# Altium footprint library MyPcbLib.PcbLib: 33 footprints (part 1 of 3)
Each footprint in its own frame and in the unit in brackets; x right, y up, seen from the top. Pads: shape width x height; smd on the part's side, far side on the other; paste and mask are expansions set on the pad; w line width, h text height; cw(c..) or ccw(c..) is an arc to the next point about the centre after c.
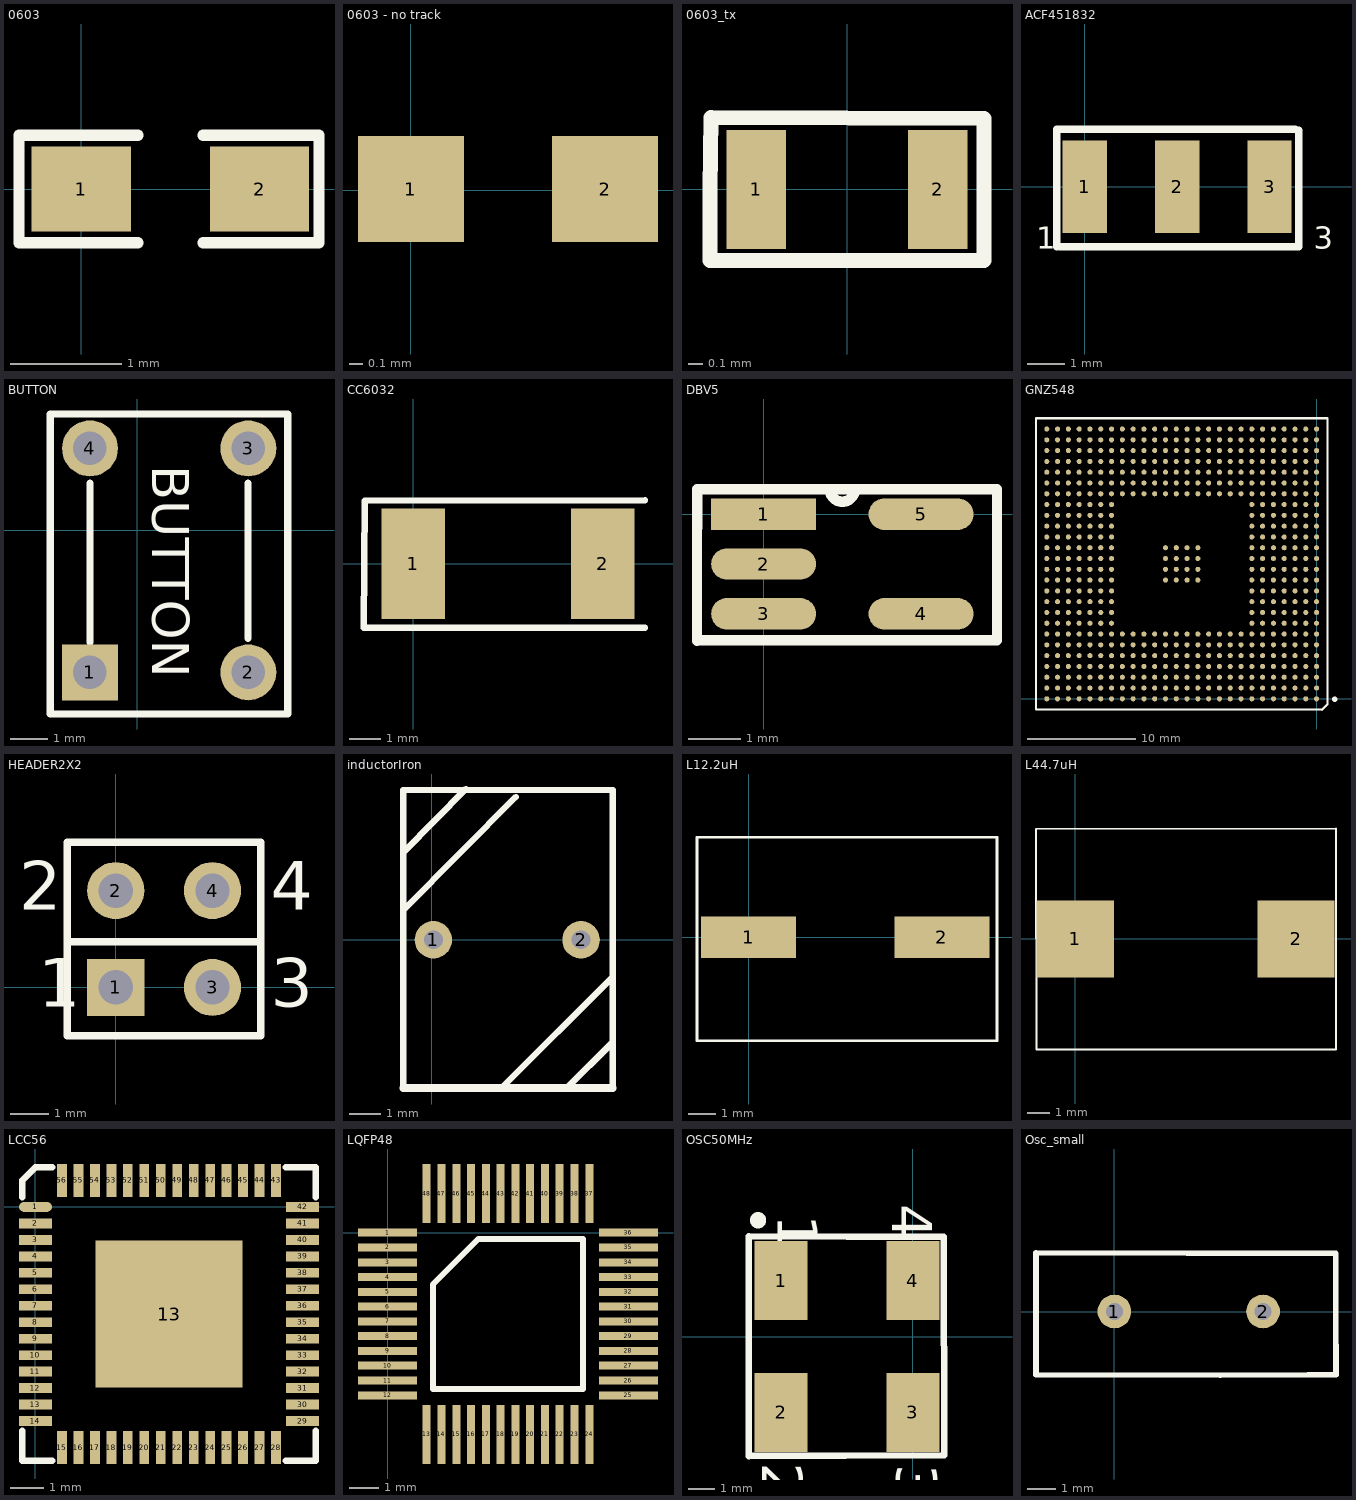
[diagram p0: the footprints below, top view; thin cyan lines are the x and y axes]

## 0603 [mil] "for DSP"
pads (2):
  rect 35x30 smd: 1(0,0) 2(62.99,0)
Top Overlay:
  lines w3.94: 20,-19 -22,-19 -22,19 20,19 ; 43,-19 84,-19 84,19 43,19

## 0603 - no track [mil]
pads (2):
  rect 30x30 smd: 1(0,0.33) 2(55,0.33)

## 0603_tx [mm]
pads (2):
  rect 0.4x0.8 smd: 1(-0.61,0) 2(0.61,0)
Top Overlay:
  lines w0.1: -0.922,-0.478 0.922,-0.478 0.922,0.478 -0.914,0.483 -0.922,0 -0.922,-0.478

## ACF451832 [mm] "for ACF451832-333-T"
pads (3):
  rect 1.2x2.5 smd: 1(0,0) 2(2.5,0) 3(5,0)
Top Overlay:
  lines w0.2: -0.762,-1.626 -0.762,1.524 ; -0.762,1.549 5.69,1.549 ; -0.686,-1.626 5.791,-1.626 5.791,1.524
  text "3" at 6.198,-1.676 h0.6
  text "1" at -1.321,-1.676 h0.6

## BUTTON [mm]
pads (4):
  rect 1.5x1.5 hole 0.9: 1(-1.27,-3.81)
  round 1.5 hole 0.9: 2(2.98,-3.81) 3(2.98,2.2) 4(-1.27,2.2)
Top Overlay:
  lines w0.2: -1.27,-2.997 -1.27,1.27 ; 2.972,-2.896 2.972,1.27 ; -2.337,-4.928 -2.337,3.124 4.039,3.124 4.039,-4.928 -2.337,-4.928
  text "BUTTON" at 0.406,1.753 h1

## CC6032 [mm] "for 100uF"
pads (2):
  rect 2x3.5 smd: 1(0,0) 2(6,0)
Top Overlay:
  lines w0.2: 7.341,-2.032 -1.564,-2.035 -1.539,1.984 7.341,2.007

## DBV5 [mm] "DBV5;DBV (R-PDSO-G5);PSO;for TPS3823-33"
pads (5):
  rect 2x0.6 smd: 1(0,0)
  oval 2x0.6 smd: 2(0,-0.95) 3(0,-1.9) 4(3,-1.9) 5(3,0)
Top Overlay:
  lines w0.2: -1.27,-2.413 -1.27,-1.067 -1.269,0.475 1.737,0.475 cw(c1.5,0.475) 1.262,0.475 4.447,0.475 4.447,-2.4 -1.257,-2.4

## GNZ548 [mm] "BGA;548 Balls;Body 27 x 27 mm;for DM642"
height 2.8
pads (548):
  round 0.47 smd: A1(0,0) A2(-1,0) A3(-2,0) A4(-3,0) A5(-4,0) A6(-5,0) A7(-6,0) A8(-7,0) A9(-8,0) A10(-9,0) A11(-10,0) A12(-11,0) A13(-12,0) A14(-13,0) A15(-14,0) A16(-15,0) A17(-16,0) A18(-17,0) A19(-18,0) A20(-19,0) A21(-20,0) A22(-21,0) A23(-22,0) A24(-23,0) A25(-24,0) A26(-25,0) AA1(0,20) AA2(-1,20) AA3(-2,20) AA4(-3,20) AA5(-4,20) AA6(-5,20) AA7(-6,20) AA8(-7,20) AA9(-8,20) AA10(-9,20) AA11(-10,20) AA12(-11,20) AA13(-12,20) AA14(-13,20) AA15(-14,20) AA16(-15,20) AA17(-16,20) AA18(-17,20) AA19(-18,20) AA20(-19,20) AA21(-20,20) AA22(-21,20) AA23(-22,20) AA24(-23,20) AA25(-24,20) AA26(-25,20) AB1(0,21) AB2(-1,21) AB3(-2,21) AB4(-3,21) AB5(-4,21) AB6(-5,21) AB7(-6,21) AB8(-7,21) AB9(-8,21) AB10(-9,21) AB11(-10,21) AB12(-11,21) AB13(-12,21) AB14(-13,21) AB15(-14,21) AB16(-15,21) AB17(-16,21) AB18(-17,21) AB19(-18,21) AB20(-19,21) AB21(-20,21) AB22(-21,21) AB23(-22,21) AB24(-23,21) AB25(-24,21) AB26(-25,21) AC1(0,22) AC2(-1,22) AC3(-2,22) AC4(-3,22) AC5(-4,22) AC6(-5,22) AC7(-6,22) AC8(-7,22) AC9(-8,22) AC10(-9,22) AC11(-10,22) AC12(-11,22) AC13(-12,22) AC14(-13,22) AC15(-14,22) AC16(-15,22) AC17(-16,22) AC18(-17,22) AC19(-18,22) AC20(-19,22) AC21(-20,22) AC22(-21,22) AC23(-22,22) AC24(-23,22) AC25(-24,22) AC26(-25,22) AD1(0,23) AD2(-1,23) AD3(-2,23) AD4(-3,23) AD5(-4,23) AD6(-5,23) AD7(-6,23) AD8(-7,23) AD9(-8,23) AD10(-9,23) AD11(-10,23) AD12(-11,23) AD13(-12,23) AD14(-13,23) AD15(-14,23) AD16(-15,23) AD17(-16,23) AD18(-17,23) AD19(-18,23) AD20(-19,23) AD21(-20,23) AD22(-21,23) AD23(-22,23) AD24(-23,23) AD25(-24,23) AD26(-25,23) AE1(0,24) AE2(-1,24) AE3(-2,24) AE4(-3,24) AE5(-4,24) AE6(-5,24) AE7(-6,24) AE8(-7,24) AE9(-8,24) AE10(-9,24) AE11(-10,24) AE12(-11,24) AE13(-12,24) AE14(-13,24) AE15(-14,24) AE16(-15,24) AE17(-16,24) AE18(-17,24) AE19(-18,24) AE20(-19,24) AE21(-20,24) AE22(-21,24) AE23(-22,24) AE24(-23,24) AE25(-24,24) AE26(-25,24) AF1(0,25) AF2(-1,25) AF3(-2,25) AF4(-3,25) AF5(-4,25) AF6(-5,25) AF7(-6,25) AF8(-7,25) AF9(-8,25) AF10(-9,25) AF11(-10,25) AF12(-11,25) AF13(-12,25) AF14(-13,25) AF15(-14,25) AF16(-15,25) AF17(-16,25) AF18(-17,25) AF19(-18,25) AF20(-19,25) AF21(-20,25) AF22(-21,25) AF23(-22,25) AF24(-23,25) AF25(-24,25) AF26(-25,25) B1(0,1) B2(-1,1) B3(-2,1) B4(-3,1) B5(-4,1) B6(-5,1) B7(-6,1) B8(-7,1) B9(-8,1) B10(-9,1) B11(-10,1) B12(-11,1) B13(-12,1) B14(-13,1) B15(-14,1) B16(-15,1) B17(-16,1) B18(-17,1) B19(-18,1) B20(-19,1) B21(-20,1) B22(-21,1) B23(-22,1) B24(-23,1) B25(-24,1) B26(-25,1) C1(0,2) C2(-1,2) C3(-2,2) C4(-3,2) C5(-4,2) C6(-5,2) C7(-6,2) C8(-7,2) C9(-8,2) C10(-9,2) C11(-10,2) C12(-11,2) C13(-12,2) C14(-13,2) C15(-14,2) C16(-15,2) C17(-16,2) C18(-17,2) C19(-18,2) C20(-19,2) C21(-20,2) C22(-21,2) C23(-22,2) C24(-23,2) C25(-24,2) C26(-25,2) D1(0,3) D2(-1,3) D3(-2,3) D4(-3,3) D5(-4,3) D6(-5,3) D7(-6,3) D8(-7,3) D9(-8,3) D10(-9,3) D11(-10,3) D12(-11,3) D13(-12,3) D14(-13,3) D15(-14,3) D16(-15,3) D17(-16,3) D18(-17,3) D19(-18,3) D20(-19,3) D21(-20,3) D22(-21,3) D23(-22,3) D24(-23,3) D25(-24,3) D26(-25,3) E1(0,4) E2(-1,4) E3(-2,4) E4(-3,4) E5(-4,4) E6(-5,4) E7(-6,4) E8(-7,4) E9(-8,4) E10(-9,4) E11(-10,4) E12(-11,4) E13(-12,4) E14(-13,4) E15(-14,4) E16(-15,4) E17(-16,4) E18(-17,4) E19(-18,4) E20(-19,4) E21(-20,4) E22(-21,4) E23(-22,4) E24(-23,4) E25(-24,4) E26(-25,4) F1(0,5) F2(-1,5) F3(-2,5) F4(-3,5) F5(-4,5) F6(-5,5) F7(-6,5) F8(-7,5) F9(-8,5) F10(-9,5) F11(-10,5) F12(-11,5) F13(-12,5) F14(-13,5) F15(-14,5) F16(-15,5) F17(-16,5) F18(-17,5) F19(-18,5) F20(-19,5) F21(-20,5) F22(-21,5) F23(-22,5) F24(-23,5) F25(-24,5) F26(-25,5) G1(0,6) G2(-1,6) G3(-2,6) G4(-3,6) G5(-4,6) G6(-5,6) G7(-6,6) G8(-7,6) G9(-8,6) G10(-9,6) G11(-10,6) G12(-11,6) G13(-12,6) G14(-13,6) G15(-14,6) G16(-15,6) G17(-16,6) G18(-17,6) G19(-18,6) G20(-19,6) G21(-20,6) G22(-21,6) G23(-22,6) G24(-23,6) G25(-24,6) G26(-25,6) H1(0,7) H2(-1,7) H3(-2,7) H4(-3,7) H5(-4,7) H6(-5,7) H7(-6,7) H20(-19,7) H21(-20,7) H22(-21,7) H23(-22,7) H24(-23,7) H25(-24,7) H26(-25,7) J1(0,8) J2(-1,8) J3(-2,8) J4(-3,8) J5(-4,8) J6(-5,8) J7(-6,8) J20(-19,8) J21(-20,8) J22(-21,8) J23(-22,8) J24(-23,8) J25(-24,8) J26(-25,8) K1(0,9) K2(-1,9) K3(-2,9) K4(-3,9) K5(-4,9) K6(-5,9) K7(-6,9) K20(-19,9) K21(-20,9) K22(-21,9) K23(-22,9) K24(-23,9) K25(-24,9) K26(-25,9) L1(0,10) L2(-1,10) L3(-2,10) L4(-3,10) L5(-4,10) L6(-5,10) L7(-6,10) L20(-19,10) L21(-20,10) L22(-21,10) L23(-22,10) L24(-23,10) L25(-24,10) L26(-25,10) M1(0,11) M2(-1,11) M3(-2,11) M4(-3,11) M5(-4,11) M6(-5,11) M7(-6,11) M12(-11,11) M13(-12,11) M14(-13,11) M15(-14,11) M20(-19,11) M21(-20,11) M22(-21,11) M23(-22,11) M24(-23,11) M25(-24,11) M26(-25,11) N1(0,12) N2(-1,12) N3(-2,12) N4(-3,12) N5(-4,12) N6(-5,12) N7(-6,12) N12(-11,12) N13(-12,12) N14(-13,12) N15(-14,12) N20(-19,12) N21(-20,12) N22(-21,12) N23(-22,12) N24(-23,12) N25(-24,12) N26(-25,12) P1(0,13) P2(-1,13) P3(-2,13) P4(-3,13) P5(-4,13) P6(-5,13) P7(-6,13) P12(-11,13) P13(-12,13) P14(-13,13) P15(-14,13) P20(-19,13) P21(-20,13) P22(-21,13) P23(-22,13) P24(-23,13) P25(-24,13) P26(-25,13) R1(0,14) R2(-1,14) R3(-2,14) R4(-3,14) R5(-4,14) R6(-5,14) R7(-6,14) R12(-11,14) R13(-12,14) R14(-13,14) R15(-14,14) R20(-19,14) R21(-20,14) R22(-21,14) R23(-22,14) R24(-23,14) R25(-24,14) R26(-25,14) T1(0,15) T2(-1,15) T3(-2,15) T4(-3,15) T5(-4,15) T6(-5,15) T7(-6,15) T20(-19,15) T21(-20,15) T22(-21,15) T23(-22,15) T24(-23,15) T25(-24,15) T26(-25,15) U1(0,16) U2(-1,16) U3(-2,16) U4(-3,16) U5(-4,16) U6(-5,16) U7(-6,16) U20(-19,16) U21(-20,16) U22(-21,16) U23(-22,16) U24(-23,16) U25(-24,16) U26(-25,16) V1(0,17) V2(-1,17) V3(-2,17) V4(-3,17) V5(-4,17) V6(-5,17) V7(-6,17) V20(-19,17) V21(-20,17) V22(-21,17) V23(-22,17) V24(-23,17) V25(-24,17) V26(-25,17) W1(0,18) W2(-1,18) W3(-2,18) W4(-3,18) W5(-4,18) W6(-5,18) W7(-6,18) W20(-19,18) W21(-20,18) W22(-21,18) W23(-22,18) W24(-23,18) W25(-24,18) W26(-25,18) Y1(0,19) Y2(-1,19) Y3(-2,19) Y4(-3,19) Y5(-4,19) Y6(-5,19) Y7(-6,19) Y8(-7,19) Y9(-8,19) Y10(-9,19) Y11(-10,19) Y12(-11,19) Y13(-12,19) Y14(-13,19) Y15(-14,19) Y16(-15,19) Y17(-16,19) Y18(-17,19) Y19(-18,19) Y20(-19,19) Y21(-20,19) Y22(-21,19) Y23(-22,19) Y24(-23,19) Y25(-24,19) Y26(-25,19)
Top Overlay:
  circle w0.25: c1.676,-0.037 r0.125
  lines w0.2: 0.5,-1 -26,-1 -26,26 1,26 1,-0.5 ; 0.508,-1.016 1.008,-0.516

## HEADER2X2 [mm]
pads (4):
  rect 1.5x1.5 hole 0.9: 1(0,0)
  round 1.5 hole 0.9: 2(0,2.54) 3(2.54,0) 4(2.54,2.54)
Top Overlay:
  lines w0.2: -1.27,1.194 3.81,1.194 ; -1.27,-1.27 -1.27,3.81 3.81,3.81 3.81,-1.27 -1.27,-1.27
  text "1" at -2.032,-0.508 h1.27
  text "2" at -2.54,2.032 h1.27
  text "4" at 4.064,2.032 h1.27
  text "3" at 4.064,-0.508 h1.27

## inductorIron [mm]
pads (2):
  round 1.2 hole 0.6: 1(0.051,0) 2(4.775,0)
Top Overlay:
  lines w0.2: -0.914,-4.75 -0.914,4.797 5.791,4.797 5.791,-4.75 ; -0.889,2.819 1.092,4.826 ; -0.864,0.991 2.692,4.572 ; 2.261,-4.724 5.766,-1.219 ; 4.293,-4.775 5.766,-3.302
  lines w0.254: -0.914,-4.75 5.791,-4.75

## L12.2uH [mm] "for 2.2uH"
pads (2):
  rect 3.5x1.54 smd: 1(0,0) 2(7.112,0)
Top Overlay:
  lines w0.102: -1.905,-3.81 9.144,-3.81 9.144,3.683 -1.905,3.683 -1.905,-3.81

## L44.7uH [mm] "for L4"
pads (2):
  rect 3.5x3.5 smd: 1(0,0) 2(10,0)
Top Overlay:
  lines w0.102: -1.778,4.978 -1.753,-5.004 11.811,-5 11.811,5 -1.778,4.978

## LCC56 [mm] "for ISP1582"
pads (57):
  oval 1x0.3 smd: 1(0,0)
  rect 1x0.3 smd: 2(0,-0.5) 3(0,-1) 4(0,-1.5) 5(0,-2) 6(0,-2.5) 7(0,-3) 8(0,-3.5) 9(0,-4) 10(0,-4.5) 11(0,-5) 12(0,-5.5) 13(0,-6) 14(0,-6.5) 29(8.1,-6.5) 30(8.1,-6) 31(8.1,-5.5) 32(8.1,-5) 33(8.1,-4.5) 34(8.1,-4) 35(8.1,-3.5) 36(8.1,-3) 37(8.1,-2.5) 38(8.1,-2) 39(8.1,-1.5) 40(8.1,-1) 41(8.1,-0.5) 42(8.1,0)
  rect 4.45x4.45 smd: 13(4.05,-3.25)
  rect 0.3x1 smd: 15(0.8,-7.3) 16(1.3,-7.3) 17(1.8,-7.3) 18(2.3,-7.3) 19(2.8,-7.3) 20(3.3,-7.3) 21(3.8,-7.3) 22(4.3,-7.3) 23(4.8,-7.3) 24(5.3,-7.3) 25(5.8,-7.3) 26(6.3,-7.3) 27(6.8,-7.3) 28(7.3,-7.3) 43(7.3,0.8) 44(6.8,0.8) 45(6.3,0.8) 46(5.8,0.8) 47(5.3,0.8) 48(4.8,0.8) 49(4.3,0.8) 50(3.8,0.8) 51(3.3,0.8) 52(2.8,0.8) 53(2.3,0.8) 54(1.8,0.8) 55(1.3,0.8) 56(0.8,0.8)
Top Overlay:
  lines w0.2: -0.4,-6.8 -0.4,-7.7 0.5,-7.7 ; -0.4,0.3 -0.4,0.8 0,1.2 0.5,1.2 ; 7.6,-7.7 8.5,-7.7 8.5,-6.8 ; 7.6,1.2 8.5,1.2 8.5,0.3

## LQFP48 [mm] "LQFP48;for SC16C550"
pads (48):
  rect 2x0.27 smd: 1(0,0) 2(0,-0.5) 3(0,-1) 4(0,-1.5) 5(0,-2) 6(0,-2.5) 7(0,-3) 8(0,-3.5) 9(0,-4) 10(0,-4.5) 11(0,-5) 12(0,-5.5) 25(8.15,-5.5) 26(8.15,-5) 27(8.15,-4.5) 28(8.15,-4) 29(8.15,-3.5) 30(8.15,-3) 31(8.15,-2.5) 32(8.15,-2) 33(8.15,-1.5) 34(8.15,-1) 35(8.15,-0.5) 36(8.15,0)
  rect 0.27x2 smd: 13(1.325,-6.825) 14(1.825,-6.825) 15(2.325,-6.825) 16(2.825,-6.825) 17(3.325,-6.825) 18(3.825,-6.825) 19(4.325,-6.825) 20(4.825,-6.825) 21(5.325,-6.825) 22(5.825,-6.825) 23(6.325,-6.825) 24(6.825,-6.825) 37(6.825,1.325) 38(6.325,1.325) 39(5.825,1.325) 40(5.325,1.325) 41(4.825,1.325) 42(4.325,1.325) 43(3.825,1.325) 44(3.325,1.325) 45(2.825,1.325) 46(2.325,1.325) 47(1.825,1.325) 48(1.325,1.325)
Top Overlay:
  lines w0.2: 1.535,-5.29 6.615,-5.29 6.615,-0.21 3.07,-0.21 1.535,-1.745 1.535,-5.29

## OSC50MHz [mm] "for 50MHz"
pads (4):
  rect 2x3 smd: 1(-5,2.134) 2(-5,-2.87) 3(0,-2.866) 4(0,2.134)
Top Overlay:
  circle w0.5: c-5.873,4.42 r0.057
  lines w0.254: -6.223,-4.521 -6.223,3.81 1.168,3.785 1.194,-4.496 -6.223,-4.521
  text "4" at -0.787,5.029 h1.52
  text "3" at -0.61,-4.826 h1.52
  text "2" at -5.715,-4.775 h1.52
  text "1" at -5.131,4.623 h1.52

## Osc_small [mm] "for 14.31818MHz Oscillator"
pads (2):
  round 1.2 hole 0.6: 1(0,0) 2(5.3,0)
Top Overlay:
  lines w0.2: -2.794,-2.261 -2.793,2.094 7.89,2.068 7.89,-0.051 7.899,-2.261 6.909,-2.261 3.775,-2.271 -2.794,-2.261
